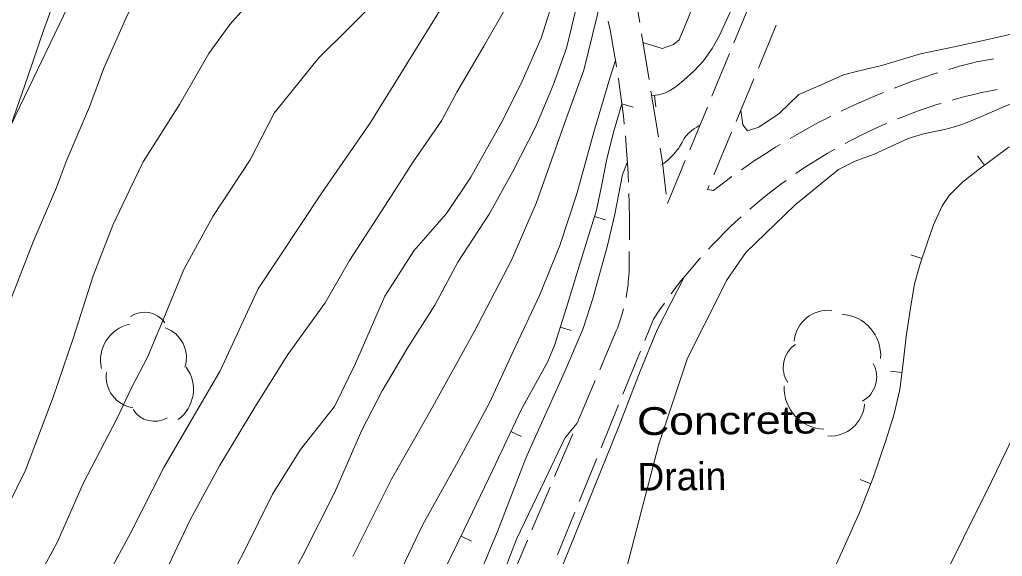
# Model space of a CAD drawing. Extents: x 2361284 to 2366480, y 6976556 to 6985346.
# Drawn here: x 2364623.7 to 2364793.5, y 6979834.6 to 6979927.3 of the extents above; entities that cross this region are included whole.
import ezdxf

# ---------------------------------------------------------------- set-up
doc = ezdxf.new("R2010")
doc.units = 0
doc.header["$LTSCALE"] = 1.9
for name, color, linetype, lineweight in [('12', 7, 'Continuous', 13), ('13', 7, 'Continuous', 13), ('16', 7, 'Continuous', 13), ('3', 7, 'Continuous', 13), ('30', 7, 'Continuous', 13), ('6', 7, 'Continuous', 13)]:
    doc.layers.add(name, color=color, linetype=linetype, lineweight=lineweight)

msp = doc.modelspace()

# ---------------------------------------------------------------- linework, layer by layer
at = {"layer": '12'}
for points in [[(2364642.995, 6979962.99), (2364641.068, 6979958.481), (2364637.988, 6979951.132), (2364635.866, 6979946.031), (2364632.832, 6979938.002), (2364630.353, 6979932.577), (2364627.781, 6979925.434), (2364625.086, 6979917.458), (2364622.156, 6979909.038), (2364619.274, 6979901.951), (2364615.91, 6979892.939), (2364611.993, 6979882.06), (2364609.831, 6979874.97), (2364606.605, 6979865.948), (2364602.482, 6979855.789), (2364599.035, 6979847.016), (2364595.73, 6979837.044), (2364594.451, 6979832.771)], [(2364713.098, 6979961.976), (2364714.158, 6979958.816), (2364713.957, 6979952.614), (2364713.347, 6979946.278), (2364712.676, 6979939.061), (2364710.234, 6979933.987), (2364707.511, 6979929.071), (2364703.862, 6979922.697), (2364699.197, 6979914.782), (2364696.563, 6979909.806), (2364691.65, 6979902.759), (2364686.832, 6979895.184), (2364680.682, 6979885.684), (2364676.462, 6979878.393), (2364670.025, 6979869.493), (2364664.322, 6979860.367), (2364658.168, 6979850.248), (2364653.115, 6979840.96), (2364647.312, 6979828.694)]]:
    msp.add_lwpolyline(points, dxfattribs=at)
at = {"layer": '13'}
for points in [[(2364695.953, 6980023.457), (2364691.127, 6980016.68), (2364687.13, 6980008.953), (2364682.132, 6980001.395), (2364679.885, 6979995.792), (2364675.279, 6979986.908), (2364673.65, 6979983.622), (2364667.375, 6979974.642), (2364663.372, 6979969.724), (2364658.2, 6979961.484), (2364653.066, 6979953.345), (2364651.106, 6979948.086), (2364647.921, 6979941.316), (2364644.659, 6979933.143), (2364642.033, 6979927.478), (2364638.214, 6979918.892), (2364635.747, 6979912.228), (2364631.676, 6979902.819), (2364630.019, 6979898.303), (2364625.988, 6979888.914), (2364621.889, 6979878.374)], [(2364782.57, 6980023.211), (2364779.039, 6980013.816), (2364775.115, 6980005.809), (2364770.08, 6979994.73), (2364766.998, 6979986.54), (2364761.481, 6979976.587), (2364756.815, 6979968.932), (2364752.909, 6979960.085), (2364749.572, 6979951.283), (2364744.35, 6979939.932), (2364741.332, 6979933.252), (2364739.206, 6979927.572), (2364737.622, 6979923.838), (2364736.62, 6979922.978), (2364734.676, 6979922.34), (2364731.367, 6979923.358)], [(2364700.362, 6979974.246), (2364701.587, 6979971.627), (2364703.866, 6979969.579), (2364706.631, 6979963.765), (2364707.947, 6979956.837), (2364705.92, 6979949.128), (2364702.692, 6979939.526), (2364696.843, 6979929.789), (2364684.275, 6979909.529), (2364675.881, 6979897.37), (2364664.898, 6979880.803), (2364658.332, 6979866.66), (2364648.58, 6979849.977), (2364642.817, 6979838.642), (2364635.113, 6979824.348)], [(2364717.764, 6979952.93), (2364718.162, 6979953.114), (2364719.163, 6979951.662), (2364717.895, 6979945.451), (2364717.358, 6979939.936), (2364716.38, 6979932.305), (2364713.768, 6979924.111), (2364710.244, 6979916.137), (2364706.975, 6979909.675), (2364701.637, 6979900.074), (2364697.405, 6979893.804), (2364691.776, 6979887.389), (2364686.761, 6979879.541), (2364681.721, 6979867.953), (2364678.042, 6979860.527), (2364672.201, 6979853.082), (2364667.375, 6979845.364), (2364662.487, 6979835.578), (2364658.52, 6979827.96)], [(2364721.915, 6979941.399), (2364720.61, 6979937.737), (2364719.887, 6979929.508), (2364718.145, 6979922.353), (2364715.876, 6979915.961), (2364712.833, 6979908.85), (2364708.907, 6979901.103), (2364704.768, 6979893.714), (2364699.356, 6979885.411), (2364695.386, 6979878.003), (2364690.765, 6979870.689), (2364686.286, 6979863.186), (2364682.81, 6979856.433), (2364678.084, 6979845.616), (2364672.585, 6979834.794), (2364668.084, 6979826.491)], [(2364686.533, 6979931.921), (2364680.59, 6979925.886), (2364675.319, 6979920.635), (2364667.649, 6979911.131), (2364663.516, 6979903.091), (2364657.059, 6979893.28), (2364652.024, 6979884.171), (2364648.164, 6979874.764), (2364645.739, 6979869.032), (2364643.068, 6979863.815), (2364640.539, 6979858.471), (2364634.715, 6979847.305), (2364630.121, 6979837.041), (2364624.638, 6979826.858)], [(2364664.327, 6979931.36), (2364659.963, 6979926.439), (2364656.371, 6979921.435), (2364651.293, 6979912.666), (2364644.988, 6979902.775), (2364642.634, 6979897.853), (2364639.772, 6979891.786), (2364636.385, 6979883.072), (2364632.888, 6979872.239), (2364629.453, 6979862.086), (2364624.692, 6979849.53), (2364618.649, 6979837.312)], [(2364724.266, 6979931.85), (2364723.521, 6979928.193), (2364721.132, 6979918.591), (2364718.179, 6979910.331), (2364712.998, 6979895.722), (2364708.711, 6979885.86), (2364702.191, 6979873.388), (2364694.462, 6979859.454), (2364687.911, 6979847.931), (2364681.228, 6979834.597)], [(2364827.046, 6979926.038), (2364827.14, 6979927.679), (2364825.71, 6979928.705), (2364821.905, 6979929.228), (2364818.171, 6979928.603), (2364811.903, 6979927.404), (2364803.92, 6979926.558), (2364798.768, 6979925.679), (2364790.416, 6979923.78), (2364785.127, 6979922.579), (2364779.338, 6979921.414), (2364772.836, 6979919.462), (2364768.256, 6979918.329), (2364766.002, 6979917.747), (2364762.545, 6979916.234), (2364758.294, 6979914.384), (2364754.915, 6979911.091), (2364751.407, 6979908.717), (2364749.443, 6979908.118), (2364748.623, 6979909.141), (2364748.289, 6979911.688)], [(2364726.646, 6979920.233), (2364725.625, 6979917.203), (2364722.904, 6979907.846), (2364719.954, 6979897.249), (2364716.999, 6979888.289), (2364713.5, 6979879.685), (2364708.942, 6979870.023), (2364704.878, 6979861.113), (2364699.168, 6979850.538), (2364693.316, 6979840.102), (2364687.256, 6979827.444)], [(2364768.064, 6979902.835), (2364771.322, 6979904.086), (2364777.217, 6979906.772), (2364779.854, 6979907.554), (2364783.456, 6979908.32), (2364785.228, 6979908.779), (2364786.8, 6979909.305), (2364789.885, 6979910.563), (2364793.968, 6979912.36), (2364796.037, 6979913.171), (2364798.15, 6979913.841), (2364799.228, 6979914.103), (2364800.665, 6979914.363), (2364803.571, 6979914.659), (2364809.422, 6979914.966), (2364812.318, 6979915.328), (2364817.229, 6979916.254), (2364821.372, 6979916.934), (2364823.324, 6979917.343), (2364824.286, 6979917.641), (2364825.445, 6979918.23), (2364826.137, 6979918.755), (2364827.393, 6979919.991)], [(2364741.163, 6979909), (2364740.86, 6979908.857), (2364740.664, 6979908.753), (2364740.283, 6979908.522), (2364740.1, 6979908.396), (2364739.745, 6979908.124), (2364739.409, 6979907.826), (2364739.195, 6979907.613), (2364739.056, 6979907.466), (2364738.79, 6979907.157), (2364738.612, 6979906.921), (2364738.504, 6979906.759), (2364738.305, 6979906.429), (2364738.121, 6979906.093), (2364737.877, 6979905.647), (2364737.749, 6979905.428), (2364737.538, 6979905.108), (2364737.421, 6979904.954), (2364736.938, 6979904.365), (2364736.692, 6979904.081), (2364736.311, 6979903.669), (2364735.908, 6979903.274), (2364735.696, 6979903.084), (2364735.247, 6979902.717), (2364735.007, 6979902.541), (2364734.626, 6979902.287)], [(2364728.673, 6979902.751), (2364727.834, 6979900.563), (2364726.519, 6979893.721), (2364725.25, 6979888.328), (2364722.707, 6979879.163), (2364721.056, 6979873.957), (2364717.786, 6979866.446), (2364712.812, 6979855.308), (2364711.108, 6979851.571), (2364706.258, 6979838.945), (2364701.868, 6979828.423)], [(2364727.574, 6979828.957), (2364730.74, 6979840.978), (2364734.086, 6979854.01), (2364739.065, 6979868.819), (2364744.818, 6979880.233), (2364745.818, 6979882.283), (2364749.121, 6979887.098), (2364757.654, 6979895.347), (2364765.167, 6979901.398), (2364768.064, 6979902.835)], [(2364702.839, 6979796.829), (2364727.227, 6979857.045), (2364730.867, 6979866.59), (2364733.809, 6979873.728), (2364738.551, 6979882.934)], [(2364781.895, 6979828.073), (2364791.61, 6979847.577), (2364799.153, 6979863.129)], [(2364719.961, 6979857.546), (2364717.855, 6979855.026), (2364714.355, 6979847.692), (2364709.52, 6979837.606), (2364705.94, 6979828.261)]]:
    msp.add_lwpolyline(points, dxfattribs=at)
at = {"layer": '16'}
for centre, radius, start, end in [((2364645.237, 6979872.483), 4.297, 34.56001, 124.56001), ((2364763.392, 6979871.166), 5.956, 84.08691, 174.08691), ((2364765.303, 6979869.297), 7.144, 356.14075, 86.14075), ((2364644.084, 6979868.448), 6.449, 102.67209, 192.67209), ((2364647.105, 6979868.968), 5.377, 341.77121, 71.77121), ((2364760.363, 6979867.263), 4.76, 123.69839, 213.69839), ((2364766.992, 6979865.6), 4.76, 298.93653, 28.93653), ((2364643.985, 6979865.631), 5.377, 171.90751, 261.90751), ((2364647.247, 6979863.456), 6.449, 306.35172, 36.35172), ((2364762.916, 6979863.716), 7.144, 177.84479, 267.84479), ((2364763.723, 6979861.357), 5.956, 265.86341, 355.86341), ((2364646.921, 6979862.234), 4.297, 211.54005, 301.54005)]:
    msp.add_arc(centre, radius, start, end, dxfattribs=at)
at = {"layer": '3'}
msp.add_lwpolyline([(2364804.423, 6980230.16), (2364778.606, 6980185.768), (2364765.554, 6980163.656), (2364725.497, 6980096.821), (2364701.016, 6980055.688), (2364688.849, 6980035.078), (2364670.696, 6980004.096), (2364664.925, 6979993.995), (2364661.171, 6979987.211), (2364653.861, 6979973.537), (2364650.293, 6979966.653), (2364643.299, 6979952.809), (2364636.454, 6979938.883), (2364623.019, 6979910.887), (2364614.512, 6979892.682), (2364610.376, 6979883.535), (2364604.334, 6979869.743), (2364598.505, 6979855.852), (2364595.677, 6979848.864), (2364590.438, 6979835.364), (2364587.094, 6979826.315), (2364584.929, 6979820.26), (2364580.744, 6979808.09)], dxfattribs=at)
for radius in [1898.732, 1899.692]:
    msp.add_arc((2363152.153, 6980637.949), radius, 328.94993, 336.33464, dxfattribs=at)
at = {"layer": '30'}
for p, q in [((2364733.374, 6979914.227), (2364733.603, 6979912.238)), ((2364727.738, 6979912.733), (2364729.653, 6979912.17)), ((2364790.381, 6979902.177), (2364789.197, 6979903.786)), ((2364722.982, 6979893.317), (2364724.888, 6979892.735)), ((2364779.564, 6979886.034), (2364777.678, 6979886.676)), ((2364717.083, 6979874.209), (2364718.989, 6979873.597)), ((2364776.131, 6979866.37), (2364774.148, 6979866.621)), ((2364708.554, 6979856.167), (2364710.362, 6979855.315)), ((2364770.763, 6979847.158), (2364768.896, 6979847.891)), ((2364699.926, 6979838.125), (2364701.724, 6979837.252))]:
    msp.add_line(p, q, dxfattribs=at)
for points in [[(2364771.533, 6979982.854), (2364768.929, 6979978.038), (2364766.435, 6979973.164), (2364762.325, 6979964.645), (2364758.337, 6979956.075), (2364755.673, 6979950.151), (2364753.06, 6979944.195), (2364750.918, 6979939.085), (2364748.807, 6979933.964), (2364746.742, 6979929.244), (2364744.586, 6979924.564), (2364743.338, 6979922.292), (2364741.807, 6979920.177), (2364740.193, 6979918.462), (2364738.448, 6979916.875), (2364737.327, 6979915.925), (2364736.065, 6979915.063), (2364735.279, 6979914.675), (2364734.082, 6979914.314), (2364732.874, 6979914.172)], [(2364727.738, 6979912.733), (2364726.362, 6979908.029), (2364725.148, 6979903.287), (2364724.29, 6979898.84), (2364723.312, 6979894.42), (2364721.721, 6979889.194), (2364720.11, 6979883.978), (2364718.161, 6979877.59), (2364716.131, 6979871.22), (2364714.909, 6979868.299), (2364710.328, 6979859.904), (2364705.417, 6979849.567), (2364700.475, 6979839.24), (2364695.913, 6979829.916), (2364691.331, 6979820.611), (2364687.337, 6979812.594), (2364683.343, 6979804.575), (2364680.312, 6979798.355), (2364677.342, 6979792.117), (2364674.672, 6979785.712), (2364671.963, 6979779.325), (2364669.204, 6979773.919), (2364667.417, 6979770.471)], [(2364763.971, 6979831.463), (2364766.381, 6979836.816), (2364768.811, 6979842.17), (2364771.222, 6979848.353), (2364773.362, 6979854.643), (2364774.731, 6979859.007), (2364775.759, 6979863.447), (2364776.345, 6979868.002), (2364776.872, 6979872.568), (2364777.519, 6979877.124), (2364778.305, 6979881.672), (2364779.263, 6979885.141), (2364780.43, 6979888.552), (2364781.598, 6979891.884), (2364783.048, 6979895.138), (2364784.27, 6979896.96), (2364786.589, 6979899.252), (2364789.22, 6979901.316), (2364794.661, 6979905.318)]]:
    msp.add_lwpolyline(points, dxfattribs=at)
at = {"layer": '6'}
for p, q in [((2364747.068, 6979923.308), (2364750.108, 6979930.706)), ((2364754.41, 6979926.328), (2364751.32, 6979918.948)), ((2364731.123, 6979924.836), (2364732.418, 6979916.938)), ((2364743.256, 6979914.061), (2364746.306, 6979921.46)), ((2364750.547, 6979917.1), (2364747.457, 6979909.72)), ((2364732.737, 6979914.961), (2364734.031, 6979907.062)), ((2364739.443, 6979904.813), (2364742.492, 6979912.213)), ((2364746.685, 6979907.872), (2364743.595, 6979900.493)), ((2364735.63, 6979895.568), (2364738.68, 6979902.966)), ((2364733.181, 6979875.592), (2364731.676, 6979871.888)), ((2364723.914, 6979866.834), (2364726.76, 6979873.541)), ((2364730.924, 6979870.042), (2364727.904, 6979862.632)), ((2364720.01, 6979857.626), (2364723.131, 6979864.996)), ((2364727.152, 6979860.784), (2364724.132, 6979853.375)), ((2364716.098, 6979848.429), (2364719.228, 6979855.789)), ((2364723.38, 6979851.528), (2364720.359, 6979844.118)), ((2364712.185, 6979839.231), (2364715.315, 6979846.591)), ((2364719.606, 6979842.272), (2364716.587, 6979834.863)), ((2364708.272, 6979830.033), (2364711.402, 6979837.394))]:
    msp.add_line(p, q, dxfattribs=at)
for points in [[(2364729.14, 6979934.628), (2364730.029, 6979931.575), (2364730.804, 6979926.813)], [(2364726.817, 6979919.145), (2364726.743, 6979919.594), (2364726.244, 6979922.55), (2364725.676, 6979925.514), (2364725.362, 6979927.01)], [(2364784.224, 6979918.711), (2364786.049, 6979919.248), (2364788.154, 6979919.808), (2364789.002, 6979920.036), (2364792.007, 6979920.515)], [(2364728.141, 6979909.236), (2364727.987, 6979910.685), (2364727.619, 6979913.652), (2364727.211, 6979916.638), (2364727.126, 6979917.168)], [(2364774.764, 6979915.471), (2364775.72, 6979915.84), (2364777.753, 6979916.589), (2364779.817, 6979917.309), (2364781.88, 6979917.988), (2364782.309, 6979918.122)], [(2364792.567, 6979915.25), (2364791.449, 6979915.029), (2364789.882, 6979914.694), (2364788.316, 6979914.339), (2364786.769, 6979913.945), (2364785.223, 6979913.53), (2364784.784, 6979913.406)], [(2364765.601, 6979911.482), (2364765.721, 6979911.543), (2364767.692, 6979912.473), (2364769.674, 6979913.362), (2364771.676, 6979914.211), (2364772.911, 6979914.723)], [(2364782.869, 6979912.837), (2364782.161, 6979912.621), (2364780.626, 6979912.125), (2364779.121, 6979911.601), (2364777.626, 6979911.057), (2364776.131, 6979910.482), (2364775.334, 6979910.155)], [(2364756.786, 6979906.768), (2364758.019, 6979907.49), (2364759.909, 6979908.548), (2364761.838, 6979909.576), (2364763.769, 6979910.565), (2364763.809, 6979910.585)], [(2364773.492, 6979909.387), (2364773.173, 6979909.254), (2364771.709, 6979908.6), (2364770.265, 6979907.926), (2364768.822, 6979907.223), (2364767.399, 6979906.499), (2364766.294, 6979905.909)], [(2364728.876, 6979899.263), (2364728.743, 6979901.711), (2364728.534, 6979904.7), (2364728.33, 6979907.248)], [(2364734.36, 6979905.085), (2364734.763, 6979902.609), (2364735.355, 6979897.155)], [(2364748.377, 6979901.368), (2364748.814, 6979901.672), (2364750.612, 6979902.909), (2364752.441, 6979904.097), (2364754.28, 6979905.254), (2364755.076, 6979905.742)], [(2364764.542, 6979904.952), (2364763.2, 6979904.169), (2364761.828, 6979903.346), (2364760.467, 6979902.493), (2364759.125, 6979901.63), (2364757.803, 6979900.728), (2364757.764, 6979900.707)], [(2364743.55, 6979897.813), (2364745.288, 6979899.14), (2364746.748, 6979900.212)], [(2364742.822, 6979898.646), (2364742.549, 6979897.983), (2364743.55, 6979897.813)], [(2364756.134, 6979899.552), (2364755.201, 6979898.874), (2364753.92, 6979897.912), (2364752.669, 6979896.92), (2364751.419, 6979895.908), (2364750.189, 6979894.886), (2364749.861, 6979894.593)], [(2364729.031, 6979889.264), (2364729.037, 6979889.714), (2364729.038, 6979892.705), (2364728.98, 6979895.704), (2364728.935, 6979897.264)], [(2364748.364, 6979893.269), (2364747.799, 6979892.763), (2364746.629, 6979891.672), (2364745.479, 6979890.561), (2364744.35, 6979889.419), (2364743.231, 6979888.269), (2364742.667, 6979887.653)], [(2364728.446, 6979879.298), (2364728.446, 6979879.318), (2364728.55, 6979879.859), (2364728.635, 6979880.399), (2364728.71, 6979880.94), (2364728.785, 6979881.481), (2364728.84, 6979882.031), (2364728.895, 6979882.582), (2364728.939, 6979883.122), (2364728.964, 6979883.673), (2364728.989, 6979884.213), (2364729.004, 6979884.763), (2364728.999, 6979885.313), (2364728.993, 6979885.863), (2364728.978, 6979886.413), (2364728.965, 6979886.703), (2364728.98, 6979887.263)], [(2364741.31, 6979886.18), (2364741.072, 6979885.918), (2364740.024, 6979884.698), (2364738.995, 6979883.478), (2364737.997, 6979882.238), (2364736.999, 6979880.979), (2364736.259, 6979879.982)], [(2364735.084, 6979878.371), (2364734.186, 6979877.092), (2364733.29, 6979875.763), (2364733.181, 6979875.592)], [(2364726.76, 6979873.541), (2364726.966, 6979874.053), (2364727.151, 6979874.565), (2364727.326, 6979875.087), (2364727.501, 6979875.608), (2364727.666, 6979876.13), (2364727.821, 6979876.651), (2364727.966, 6979877.183), (2364728.004, 6979877.343)]]:
    msp.add_lwpolyline(points, dxfattribs=at)

# ---------------------------------------------------------------- texts
at = {"layer": '6', "width": 1.2}
msp.add_text('Concrete', height=4.799, rotation=0.545, dxfattribs=at).set_placement((2364730.352, 6979855.555))
at = {"layer": '6'}
msp.add_text('Drain', height=4.799, rotation=0.545, dxfattribs=at).set_placement((2364730.443, 6979845.955))

doc.saveas('drawing.dxf')
